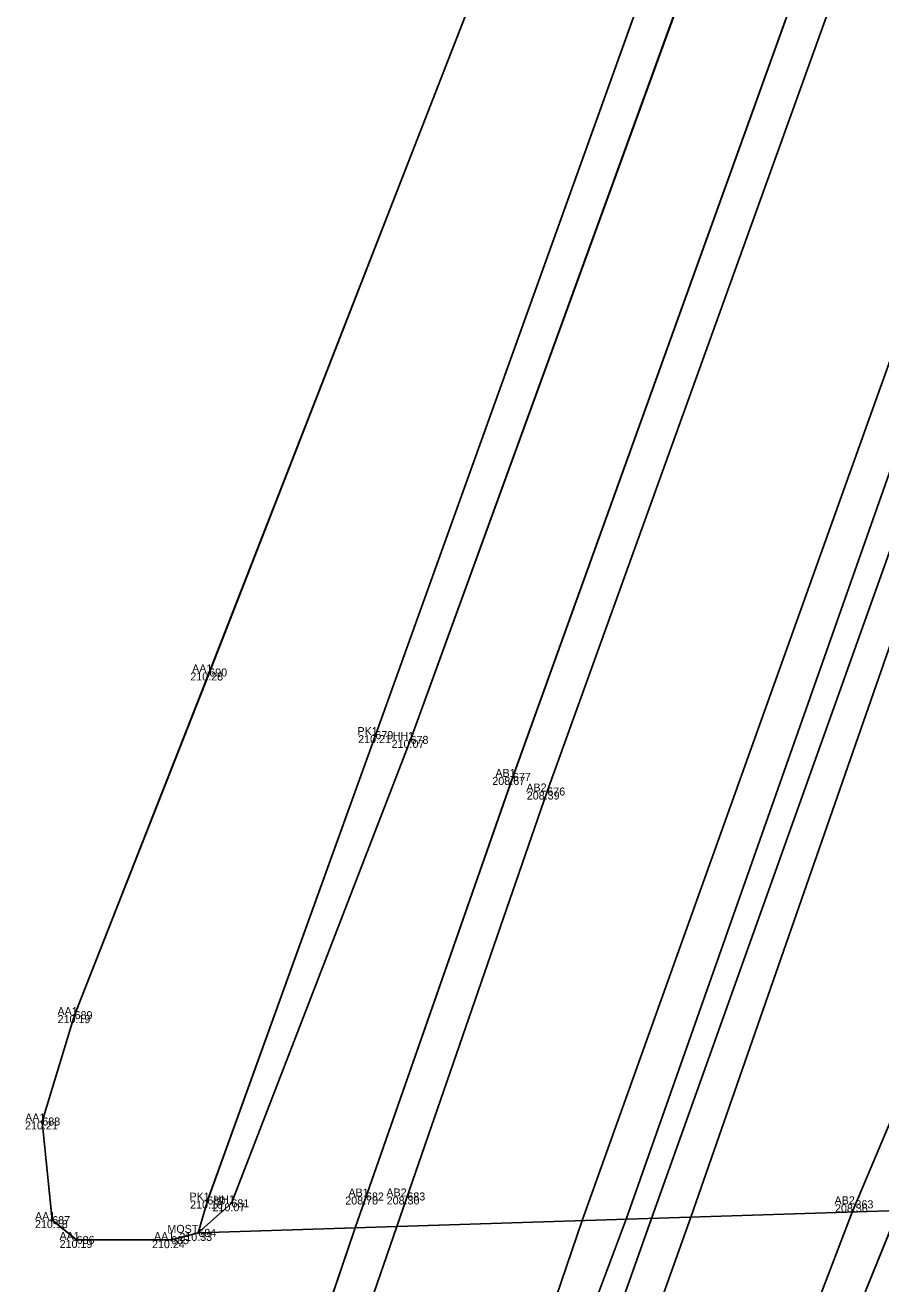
# Model space of a CAD drawing. Extents: x -263091 to -262565, y -1238731 to -1237092.
# Drawn here: x -262917 to -262895.63, y -1238240.38 to -1238208.92 of the extents above; entities that cross this region are included whole.
import ezdxf

# ---------------------------------------------------------------- set-up
doc = ezdxf.new("R2010")
doc.units = 0
for name, color, linetype in [('01_Hrana_betónu', 7, 'Continuous'), ('02_Oplotenie', 7, 'Continuous'), ('03_Asfalt', 7, 'Continuous'), ('04_Most', 7, 'Continuous'), ('05_Hrana_terénu', 7, 'Continuous'), ('Groma (21)', 7, 'Continuous'), ('Groma (22)', 7, 'Continuous'), ('Groma (23)', 7, 'Continuous'), ('Groma (24)', 7, 'Continuous'), ('U003_Betónové_panely', 7, 'Continuous'), ('U003_Zeleň_mimo', 7, 'Continuous'), ('U003_Zeleň_vnútro', 7, 'Continuous'), ('U003_Zeleň_zatrávňovač', 7, 'Continuous'), ('U005_Betóny_prídavné', 7, 'Continuous')]:
    doc.layers.add(name, color=color, linetype=linetype)

msp = doc.modelspace()

# ---------------------------------------------------------------- linework, layer by layer
at = {"layer": '01_Hrana_betónu'}
for p, q in [((-262907.17, -1238252.591), (-262901.991, -1238238.762)), ((-262906.263, -1238252.564), (-262901.352, -1238238.742)), ((-262905.311, -1238252.535), (-262900.376, -1238238.711)), ((-262901.651, -1238252.424), (-262896.34, -1238238.582)), ((-262900.833, -1238252.4), (-262895.195, -1238238.545)), ((-262913.452, -1238252.78), (-262908.762, -1238238.978)), ((-262912.516, -1238252.751), (-262907.715, -1238238.945)), ((-262907.787, -1238252.61), (-262903.088, -1238238.797))]:
    msp.add_line(p, q, dxfattribs=at)
for points in [[(-262903.088, -1238238.797), (-262890.817, -1238204.479), (-262885.468, -1238189.492), (-262878.003, -1238168.56), (-262870.455, -1238147.513), (-262864.947, -1238132.168), (-262859.037, -1238116.651), (-262848.977, -1238095.826), (-262842.353, -1238078.361), (-262839.446, -1238067.823), (-262836.783, -1238055.069), (-262834.905, -1238040.999), (-262833.763, -1238025.462), (-262832.297, -1238000.555), (-262831.13, -1237981.111), (-262829.791, -1237958.391), (-262828.651, -1237937.03), (-262828.571, -1237935.876)], [(-262827.762, -1237935.927), (-262827.853, -1237937.062), (-262829.049, -1237958.415), (-262830.305, -1237981.211), (-262831.433, -1238000.629), (-262832.987, -1238025.43), (-262834.086, -1238041.027), (-262836.169, -1238055.023), (-262838.684, -1238068.024), (-262841.681, -1238078.569), (-262848.285, -1238096.308), (-262858.162, -1238116.913), (-262863.876, -1238132.122), (-262869.919, -1238147.692), (-262877.244, -1238168.638), (-262884.69, -1238189.67), (-262901.991, -1238238.762)], [(-262827.034, -1237935.973), (-262827.072, -1237937.036), (-262828.491, -1237960.168), (-262829.643, -1237980.454), (-262830.754, -1238002.123), (-262832.4, -1238026.024), (-262833.369, -1238041.644), (-262835.263, -1238055.011), (-262838.048, -1238068.261), (-262841.826, -1238081.232), (-262846.645, -1238094.136), (-262857.777, -1238117.273), (-262863.292, -1238131.948), (-262884.082, -1238190.299), (-262901.352, -1238238.742)], [(-262900.376, -1238238.711), (-262890.192, -1238209.46), (-262883.463, -1238190.564), (-262868.512, -1238148.877), (-262862.514, -1238132.276), (-262857.014, -1238117.706), (-262845.846, -1238094.561), (-262841.058, -1238081.49), (-262837.218, -1238068.474), (-262834.492, -1238055.416), (-262832.606, -1238041.772), (-262831.509, -1238026.143), (-262830.024, -1238002.24), (-262828.826, -1237980.518), (-262827.576, -1237960.277), (-262826.117, -1237937.218), (-262826.079, -1237936.033)], [(-262908.762, -1238238.978), (-262904.818, -1238227.708), (-262897.756, -1238208.088), (-262895.676, -1238202.213), (-262890.59, -1238187.74), (-262883.178, -1238166.691), (-262875.605, -1238145.524), (-262870.177, -1238130.111), (-262864.546, -1238115.411), (-262863.698, -1238113.971), (-262862.86, -1238112.208), (-262862.02, -1238109.736), (-262852.529, -1238091.409), (-262847.756, -1238078.518), (-262845.507, -1238070.714), (-262845.277, -1238070.627)], [(-262907.715, -1238238.945), (-262903.959, -1238228.072), (-262896.871, -1238208.378), (-262894.873, -1238202.609), (-262889.743, -1238188.028), (-262882.328, -1238167.085), (-262874.744, -1238145.867), (-262869.274, -1238130.427), (-262863.367, -1238114.899), (-262851.765, -1238091.959), (-262846.929, -1238078.783), (-262844.647, -1238070.871), (-262844.833, -1238070.767)], [(-262896.34, -1238238.582), (-262893.58, -1238232.03), (-262890.694, -1238224.883), (-262885.46, -1238210.629), (-262879.076, -1238191.844), (-262872.3, -1238172.74), (-262864.174, -1238150.334), (-262858.102, -1238133.93), (-262852.288, -1238119.39), (-262842.616, -1238095.519), (-262840.924, -1238094.827)]]:
    msp.add_lwpolyline(points, dxfattribs=at)
at = {"layer": '02_Oplotenie'}
msp.add_lwpolyline([(-262912.451, -1238238.295), (-262908.254, -1238226.663), (-262901.526, -1238207.942), (-262898.552, -1238199.602), (-262894.22, -1238186.327), (-262886.794, -1238165.648), (-262879.297, -1238144.201), (-262873.976, -1238128.814), (-262867.141, -1238113.572), (-262855.316, -1238089.931), (-262850.675, -1238078.807), (-262846.261, -1238065.654), (-262843.56, -1238054.226), (-262842.344, -1238048.099), (-262841.445, -1238040.349), (-262840.733, -1238030.077), (-262839.013, -1238000.384), (-262838.353, -1237989.712), (-262835.178, -1237935.879)], dxfattribs=at)
at = {"layer": '03_Asfalt'}
msp.add_lwpolyline([(-262912.678, -1238239.103), (-262913.356, -1238239.285), (-262915.717, -1238239.279), (-262916.328, -1238238.784), (-262916.575, -1238236.319), (-262915.768, -1238233.661), (-262912.404, -1238225.097), (-262904.805, -1238205.606), (-262896.687, -1238184.948), (-262888.478, -1238163.929), (-262880.124, -1238142.63), (-262874.65, -1238128.675), (-262868.549, -1238113.075), (-262858.861, -1238088.481), (-262853.132, -1238074.038), (-262850.084, -1238066.288), (-262845.869, -1238049.471), (-262845.094, -1238038.662), (-262844.346, -1238028.542), (-262842.599, -1238000.955), (-262841.603, -1237985.168), (-262838.824, -1237943.888), (-262838.24, -1237934.633), (-262838.283, -1237933.488)], dxfattribs=at)
at = {"layer": '04_Most'}
msp.add_line((-262892.015, -1238238.444), (-262912.678, -1238239.103), dxfattribs=at)
at = {"layer": '05_Hrana_terénu'}
msp.add_lwpolyline([(-262835.062, -1237935.275), (-262834.86, -1237936.333), (-262838.087, -1237989.633), (-262838.484, -1238000.332), (-262840.387, -1238030.181), (-262840.991, -1238040.253), (-262843.126, -1238054.282), (-262845.675, -1238066.436), (-262850.413, -1238079.623), (-262854.798, -1238090.209), (-262863.856, -1238108.78), (-262866.643, -1238114.502), (-262872.333, -1238129.41), (-262877.981, -1238144.625), (-262885.616, -1238166.033), (-262893.121, -1238186.676), (-262898.244, -1238201.149), (-262900.554, -1238208.001), (-262907.375, -1238226.781), (-262911.85, -1238238.364), (-262912.678, -1238239.103)], dxfattribs=at)
at = {"layer": 'Groma (21)'}
for centre in [(-262912.404, -1238225.097), (-262908.254, -1238226.663), (-262907.375, -1238226.781), (-262904.818, -1238227.708), (-262903.959, -1238228.072), (-262915.768, -1238233.661), (-262916.575, -1238236.319), (-262912.451, -1238238.295), (-262911.85, -1238238.364), (-262908.488, -1238238.194), (-262907.455, -1238238.193), (-262896.259, -1238238.389), (-262916.328, -1238238.784), (-262915.717, -1238239.279), (-262913.356, -1238239.285), (-262912.678, -1238239.103)]:
    msp.add_circle(centre, 0.01, dxfattribs=at)
at = {"layer": 'U003_Betónové_panely'}
for points in [[(-262822, -1237934.47), (-262822.23, -1237936.28), (-262821.72, -1237936.34), (-262823.03, -1237960.34), (-262824.32, -1237980.84), (-262825.49, -1238001.86), (-262826.83, -1238026.47), (-262828.06, -1238041.94), (-262830.21, -1238056.42), (-262832.97, -1238069.04), (-262836.94, -1238083.07), (-262840.92, -1238094.83), (-262840.6, -1238094.73), (-262841.76, -1238095.81), (-262851.46, -1238119.84), (-262857.2, -1238134.12), (-262863.32, -1238150.73), (-262871.41, -1238173.11), (-262878.16, -1238192.14), (-262884.61, -1238210.94), (-262889.86, -1238225.24), (-262892.75, -1238232.5), (-262895.19, -1238238.55), (-262900.83, -1238252.4)], [(-262822, -1237934.47), (-262822.23, -1237936.28), (-262821.72, -1237936.34), (-262823.03, -1237960.34), (-262824.32, -1237980.84), (-262825.49, -1238001.86), (-262826.83, -1238026.47), (-262828.06, -1238041.94), (-262830.21, -1238056.42), (-262832.97, -1238069.04), (-262836.94, -1238083.07), (-262840.92, -1238094.83), (-262840.6, -1238094.73), (-262841.76, -1238095.81), (-262851.46, -1238119.84), (-262857.2, -1238134.12), (-262863.32, -1238150.73), (-262871.41, -1238173.11), (-262878.16, -1238192.14), (-262884.61, -1238210.94), (-262889.86, -1238225.24), (-262892.75, -1238232.5), (-262895.19, -1238238.55), (-262900.83, -1238252.4)], [(-262913.45, -1238252.78), (-262908.76, -1238238.98), (-262904.82, -1238227.71), (-262897.76, -1238208.09), (-262895.68, -1238202.21), (-262890.59, -1238187.74), (-262883.18, -1238166.69), (-262875.61, -1238145.52), (-262870.18, -1238130.11), (-262864.55, -1238115.41), (-262863.7, -1238113.97), (-262862.86, -1238112.21)], [(-262913.45, -1238252.78), (-262908.76, -1238238.98), (-262904.82, -1238227.71), (-262897.76, -1238208.09), (-262895.68, -1238202.21), (-262890.59, -1238187.74), (-262883.18, -1238166.69), (-262875.61, -1238145.52), (-262870.18, -1238130.11), (-262864.55, -1238115.41), (-262863.7, -1238113.97), (-262862.86, -1238112.21)]]:
    msp.add_lwpolyline(points, dxfattribs=at)
at = {"layer": 'U003_Zeleň_mimo'}
msp.add_lwpolyline([(-262855.32, -1238089.93), (-262867.14, -1238113.57), (-262873.98, -1238128.81), (-262879.3, -1238144.2), (-262886.79, -1238165.65), (-262894.22, -1238186.33), (-262898.55, -1238199.6), (-262901.53, -1238207.94), (-262908.25, -1238226.66), (-262912.45, -1238238.3), (-262912.68, -1238239.1), (-262913.36, -1238239.28), (-262915.72, -1238239.28), (-262916.33, -1238238.78), (-262916.58, -1238236.32), (-262915.77, -1238233.66), (-262912.4, -1238225.1), (-262904.81, -1238205.61), (-262896.69, -1238184.95), (-262888.48, -1238163.93), (-262880.12, -1238142.63), (-262874.65, -1238128.68), (-262868.55, -1238113.08), (-262858.86, -1238088.48)], dxfattribs=at)
at = {"layer": 'U003_Zeleň_vnútro'}
for points in [[(-262864.42, -1238111.37), (-262865.55, -1238113.22), (-262866.29, -1238114.68), (-262872.33, -1238129.41), (-262877.98, -1238144.63), (-262885.62, -1238166.03), (-262893.12, -1238186.68), (-262898.24, -1238201.15), (-262900.55, -1238208), (-262907.38, -1238226.78), (-262911.85, -1238238.36), (-262912.68, -1238239.1), (-262912.45, -1238238.3), (-262908.25, -1238226.66), (-262901.53, -1238207.94), (-262898.55, -1238199.6), (-262894.22, -1238186.33), (-262886.79, -1238165.65), (-262879.3, -1238144.2), (-262873.98, -1238128.81), (-262867.14, -1238113.57), (-262855.32, -1238089.93)], [(-262912.68, -1238239.1), (-262912.45, -1238238.3), (-262908.25, -1238226.66), (-262901.53, -1238207.94), (-262898.55, -1238199.6), (-262894.22, -1238186.33), (-262886.79, -1238165.65), (-262879.3, -1238144.2), (-262873.98, -1238128.81), (-262867.14, -1238113.57), (-262855.32, -1238089.93)], [(-262864.42, -1238111.37), (-262865.55, -1238113.22), (-262866.29, -1238114.68), (-262872.33, -1238129.41), (-262877.98, -1238144.63), (-262885.62, -1238166.03), (-262893.12, -1238186.68), (-262898.24, -1238201.15), (-262900.55, -1238208), (-262907.38, -1238226.78), (-262911.85, -1238238.36), (-262912.68, -1238239.1)]]:
    msp.add_lwpolyline(points, dxfattribs=at)
at = {"layer": 'U003_Zeleň_zatrávňovač'}
msp.add_lwpolyline([(-262866.29, -1238114.68), (-262864.55, -1238115.41), (-262870.18, -1238130.11), (-262875.61, -1238145.52), (-262883.18, -1238166.69), (-262890.59, -1238187.74), (-262895.68, -1238202.21), (-262897.76, -1238208.09), (-262904.82, -1238227.71), (-262908.76, -1238238.98), (-262912.68, -1238239.1), (-262911.85, -1238238.36), (-262907.38, -1238226.78), (-262900.55, -1238208), (-262898.24, -1238201.15), (-262893.12, -1238186.68), (-262885.62, -1238166.03), (-262877.98, -1238144.63), (-262872.33, -1238129.41)], close=True, dxfattribs=at)
at = {"layer": 'U005_Betóny_prídavné'}
msp.add_lwpolyline([(-262912.68, -1238239.1), (-262911.85, -1238238.36), (-262907.38, -1238226.78), (-262900.55, -1238208), (-262898.24, -1238201.15), (-262893.12, -1238186.68), (-262885.62, -1238166.03), (-262877.98, -1238144.63), (-262872.33, -1238129.41), (-262866.29, -1238114.68), (-262864.55, -1238115.41), (-262870.18, -1238130.11), (-262875.61, -1238145.52), (-262883.18, -1238166.69), (-262890.59, -1238187.74), (-262895.68, -1238202.21), (-262897.76, -1238208.09), (-262904.82, -1238227.71), (-262908.76, -1238238.98), (-262912.68, -1238239.1)], dxfattribs=at)

# ---------------------------------------------------------------- texts
at = {"layer": 'Groma (22)'}
for s, p in [('690', (-262912.404, -1238225.197)), ('679', (-262908.254, -1238226.763)), ('678', (-262907.375, -1238226.881)), ('677', (-262904.818, -1238227.808)), ('676', (-262903.959, -1238228.172)), ('689', (-262915.768, -1238233.761)), ('688', (-262916.575, -1238236.419)), ('682', (-262908.488, -1238238.294)), ('683', (-262907.455, -1238238.293)), ('680', (-262912.451, -1238238.395)), ('681', (-262911.85, -1238238.464)), ('363', (-262896.259, -1238238.489)), ('687', (-262916.328, -1238238.884)), ('684', (-262912.678, -1238239.203)), ('686', (-262915.717, -1238239.379)), ('685', (-262913.356, -1238239.385))]:
    msp.add_text(s, height=0.2, dxfattribs=at).set_placement(p)
at = {"layer": 'Groma (23)'}
for s, p in [('210.28', (-262912.877, -1238225.297)), ('210.21', (-262908.684, -1238226.863)), ('210.07', (-262907.848, -1238226.981)), ('208.67', (-262905.331, -1238227.908)), ('208.39', (-262904.471, -1238228.272)), ('210.19', (-262916.193, -1238233.861)), ('210.21', (-262917.005, -1238236.519)), ('210.18', (-262912.881, -1238238.495)), ('210.07', (-262912.323, -1238238.564)), ('208.70', (-262909.005, -1238238.394)), ('208.30', (-262907.971, -1238238.393)), ('208.36', (-262896.771, -1238238.589)), ('210.18', (-262916.758, -1238238.984)), ('210.19', (-262916.142, -1238239.479)), ('210.24', (-262913.834, -1238239.485)), ('210.33', (-262913.151, -1238239.303))]:
    msp.add_text(s, height=0.2, dxfattribs=at).set_placement(p)
at = {"layer": 'Groma (24)'}
for s, p in [('AA1', (-262912.832, -1238225.097)), ('PK1', (-262908.701, -1238226.663)), ('HH1', (-262907.822, -1238226.781)), ('AB1', (-262905.256, -1238227.708)), ('AB2', (-262904.483, -1238228.072)), ('AA1', (-262916.196, -1238233.661)), ('AA1', (-262917.003, -1238236.319)), ('PK1', (-262912.898, -1238238.295)), ('AB1', (-262908.926, -1238238.194)), ('AB2', (-262907.979, -1238238.193)), ('HH1', (-262912.297, -1238238.364)), ('AB2', (-262896.783, -1238238.389)), ('AA1', (-262916.756, -1238238.784)), ('AA1', (-262916.145, -1238239.279)), ('AA1', (-262913.784, -1238239.285)), ('MOST', (-262913.45, -1238239.103))]:
    msp.add_text(s, height=0.2, dxfattribs=at).set_placement(p)

doc.saveas('drawing.dxf')
